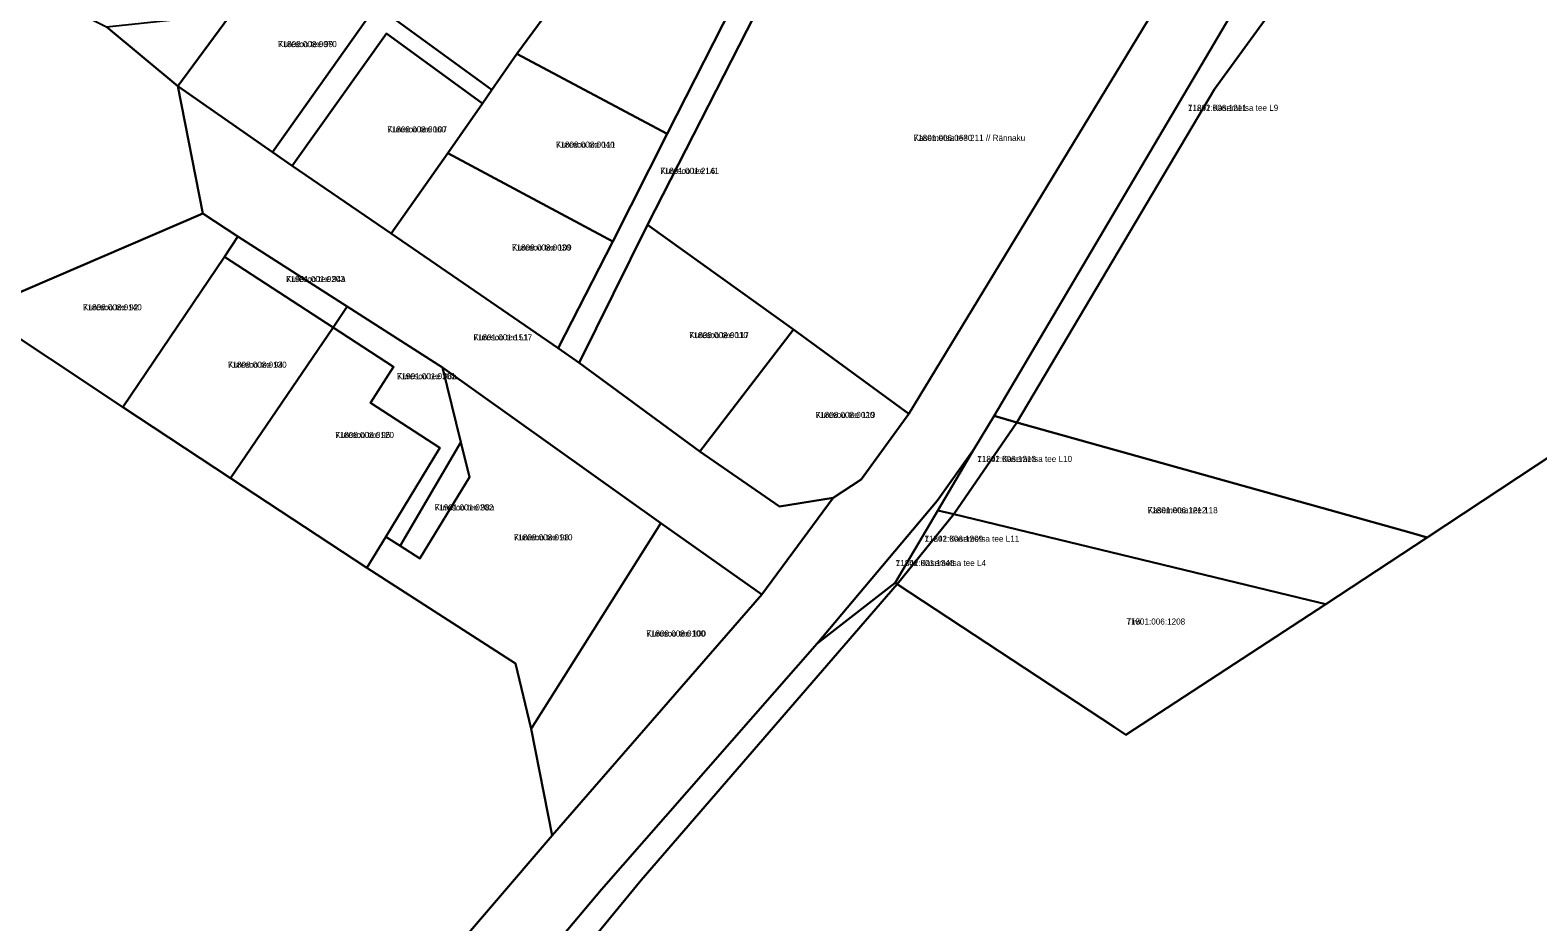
# Model space of a CAD drawing. Extents: x 529768 to 552006, y 6562269 to 6580975.
# Drawn here: x 537239.9 to 537612.3, y 6569100.3 to 6569320.5 of the extents above; entities that cross this region are included whole.
import ezdxf

# ---------------------------------------------------------------- set-up
doc = ezdxf.new("R2010")
doc.units = 0
for name, color, linetype in [('L_AADRESS', 7, 'Continuous'), ('PIIR', 7, 'Continuous'), ('TUNNUS', 7, 'Continuous')]:
    doc.layers.add(name, color=color, linetype=linetype)

msp = doc.modelspace()

# ---------------------------------------------------------------- linework, layer by layer
at = {"layer": 'PIIR'}
for points in [[(537281.43, 6569019.46), (537368.89, 6569121.58), (537420.6, 6569181.09), (537438.26, 6569204.93), (537445.15, 6569209.46), (537456.97, 6569225.74), (537523.87, 6569335.93), (537530.38, 6569351.64), (537552.48, 6569389.3), (537556.5, 6569395.83), (537567.78, 6569415.59), (537578.32, 6569433.84), (537588.9, 6569451.99), (537598.21, 6569467.74), (537645.8, 6569545.54), (537653.92, 6569559.3), (537664.42, 6569572.88), (537699.62, 6569634.71), (537702.59, 6569639.82), (537731.22, 6569689.57), (537747.58, 6569702.72), (538032.41, 6569935.34), (538189.88, 6570063.68)], [(537622.11, 6569470.11), (537568.68, 6569378.74), (537478.05, 6569225.23), (537473.1, 6569217.08), (537463.95, 6569204.19), (537434.3, 6569169.03), (537381.02, 6569108.28), (537348.18, 6569069.26)], [(537170.73, 6569376.5), (537249.6, 6569325.97), (537251.48, 6569325.01), (537257.63, 6569321.87), (537258.8, 6569321.28), (537276.4, 6569306.65), (537282.55, 6569275.19), (537226.88, 6569251.23), (537262.82, 6569227.37), (537289.45, 6569209.82), (537323.12, 6569187.65), (537359.8, 6569164.07), (537363.64, 6569147.9), (537368.89, 6569121.58), (537281.43, 6569019.46)], [(537269.76, 6568963.22), (537390.82, 6569110.56), (537454.04, 6569183.63), (537507.72, 6569148.32), (537510.55, 6569146.45), (537559.96, 6569178.74), (537584.93, 6569195.2), (537724.42, 6569287.32), (537727.95, 6569284.57), (537806.09, 6568987.59)]]:
    msp.add_lwpolyline(points, dxfattribs=at)
for points in [[(537331.41, 6569385.08), (537333.24, 6569383.74), (537303.05, 6569342.82), (537276.4, 6569306.65), (537258.8, 6569321.28), (537286.07, 6569324.15)], [(537568.68, 6569378.74), (537573.72, 6569375.48), (537557.07, 6569345.82), (537550.3, 6569330.48), (537532.46, 6569305.9), (537483.59, 6569223.61), (537478.05, 6569225.23)], [(537573.72, 6569375.48), (537721.35, 6569289.12), (537724.42, 6569287.32), (537584.93, 6569195.2), (537580.98, 6569196.31), (537483.59, 6569223.61), (537532.46, 6569305.9), (537550.3, 6569330.48), (537557.07, 6569345.82)], [(537356.02, 6569369.35), (537360.2, 6569366.7), (537329.49, 6569323.5), (537353.94, 6569305.69), (537351.65, 6569302.39), (537327.98, 6569319.65), (537304.66, 6569286.98), (537299.8, 6569290.36), (537325.92, 6569327.15)], [(537392.4, 6569272.37), (537420.72, 6569327.75), (537471.2, 6569369.35), (537523.87, 6569335.93), (537456.97, 6569225.74), (537428.48, 6569246.54)], [(537329.49, 6569323.5), (537360.2, 6569366.7), (537373.92, 6569357.84), (537386.16, 6569349.94), (537360.1, 6569314.6), (537353.94, 6569305.69)], [(537386.16, 6569349.94), (537415.64, 6569330.96), (537397.29, 6569294.89), (537360.1, 6569314.6)], [(537325.92, 6569327.15), (537299.8, 6569290.36), (537276.4, 6569306.65), (537303.05, 6569342.82)], [(537370.36, 6569241.96), (537383.8, 6569268.29), (537397.29, 6569294.89), (537415.64, 6569330.96), (537420.72, 6569327.75), (537392.4, 6569272.37), (537375.53, 6569238.29)], [(537327.98, 6569319.65), (537351.65, 6569302.39), (537343.1, 6569290.11), (537329.12, 6569270.23), (537304.66, 6569286.98)], [(537351.65, 6569302.39), (537353.94, 6569305.69), (537360.1, 6569314.6), (537397.29, 6569294.89), (537383.8, 6569268.29), (537343.1, 6569290.11)], [(537438.26, 6569204.93), (537420.6, 6569181.09), (537395.67, 6569198.74), (537341.76, 6569237.16), (537318.26, 6569252.2), (537291.25, 6569269.49), (537282.55, 6569275.19), (537276.4, 6569306.65), (537299.8, 6569290.36), (537304.66, 6569286.98), (537329.12, 6569270.23), (537370.36, 6569241.96), (537375.53, 6569238.29), (537405.33, 6569216.45), (537425.03, 6569202.85)], [(537383.8, 6569268.29), (537370.36, 6569241.96), (537329.12, 6569270.23), (537343.1, 6569290.11)], [(537282.55, 6569275.19), (537291.25, 6569269.49), (537287.93, 6569264.5), (537262.82, 6569227.37), (537226.88, 6569251.23)], [(537428.48, 6569246.54), (537405.33, 6569216.45), (537375.53, 6569238.29), (537392.4, 6569272.37)], [(537291.25, 6569269.49), (537318.26, 6569252.2), (537314.74, 6569247.04), (537287.93, 6569264.5)], [(537287.93, 6569264.5), (537314.74, 6569247.04), (537289.45, 6569209.82), (537262.82, 6569227.37)], [(537327.78, 6569195.35), (537341.1, 6569217.3), (537324.02, 6569228.41), (537329.65, 6569237.34), (537314.74, 6569247.04), (537318.26, 6569252.2), (537341.76, 6569237.16), (537346.31, 6569218.69), (537331.28, 6569193.13)], [(537314.74, 6569247.04), (537329.65, 6569237.34), (537324.02, 6569228.41), (537341.1, 6569217.3), (537327.78, 6569195.35), (537323.12, 6569187.65), (537289.45, 6569209.82)], [(537405.33, 6569216.45), (537428.48, 6569246.54), (537456.97, 6569225.74), (537445.15, 6569209.46), (537438.26, 6569204.93), (537425.03, 6569202.85)], [(537323.12, 6569187.65), (537327.78, 6569195.35), (537331.28, 6569193.13), (537336.2, 6569190), (537348.42, 6569210.1), (537346.31, 6569218.69), (537341.76, 6569237.16), (537395.67, 6569198.74), (537363.64, 6569147.9), (537359.8, 6569164.07)], [(537478.05, 6569225.23), (537483.59, 6569223.61), (537468.07, 6569200.9), (537464.1, 6569201.88), (537473.1, 6569217.08)], [(537483.59, 6569223.61), (537580.98, 6569196.31), (537584.93, 6569195.2), (537559.96, 6569178.74), (537555.84, 6569179.73), (537468.07, 6569200.9)], [(537336.2, 6569190), (537331.28, 6569193.13), (537346.31, 6569218.69), (537348.42, 6569210.1)], [(537463.95, 6569204.19), (537473.1, 6569217.08), (537464.1, 6569201.88), (537453.54, 6569183.95), (537434.3, 6569169.03)], [(537464.1, 6569201.88), (537468.07, 6569200.9), (537454.04, 6569183.63), (537453.54, 6569183.95)], [(537420.6, 6569181.09), (537368.89, 6569121.58), (537363.64, 6569147.9), (537395.67, 6569198.74)], [(537468.07, 6569200.9), (537555.84, 6569179.73), (537559.96, 6569178.74), (537510.55, 6569146.45), (537507.72, 6569148.32), (537454.04, 6569183.63)], [(537381.02, 6569108.28), (537434.3, 6569169.03), (537453.54, 6569183.95), (537454.04, 6569183.63), (537390.82, 6569110.56), (537269.76, 6568963.22), (537215.48, 6568889.87), (537209.84, 6568896.55), (537232.31, 6568928.74), (537261.02, 6568964.25), (537348.18, 6569069.26)]]:
    msp.add_lwpolyline(points, close=True, dxfattribs=at)

# ---------------------------------------------------------------- texts
at = {"layer": 'L_AADRESS'}
for s, p in [('Kuresoo tee 99', (537301.16, 6569316.27)), ('11242 Kasemetsa tee L9', (537525.88, 6569300.54)), ('Kuresoo tee 107', (537328.15, 6569295.21)), ('Kasemetsa tee 211 // Rännaku', (537458.13, 6569293.12)), ('Kuresoo tee 111', (537369.79, 6569291.45)), ('Kuresoo tee L6', (537395.54, 6569284.97)), ('Kuresoo tee 109', (537358.94, 6569266.04)), ('Kuresoo tee 94a', (537303.14, 6569258.26)), ('Kuresoo tee 92', (537252.99, 6569251.28)), ('Kuresoo tee 117', (537402.7, 6569244.41)), ('Kuresoo tee L1', (537349.42, 6569243.87)), ('Kuresoo tee 94', (537288.78, 6569237.1)), ('Kuresoo tee 96a', (537330.53, 6569234.26)), ('Kuresoo tee 119', (537433.94, 6569224.7)), ('Kuresoo tee 96', (537315.28, 6569219.75)), ('11242 Kasemetsa tee L10', (537473.85, 6569213.83)), ('Kuresoo tee 98a', (537339.85, 6569201.85)), ('Kasemetsa tee 118', (537515.94, 6569201.17)), ('Kuresoo tee 98', (537359.39, 6569194.46)), ('11242 Kasemetsa tee L11', (537460.8, 6569194.12)), ('11242 Kasemetsa tee L4', (537453.7, 6569188.13)), ('Tiivi', (537510.69, 6569173.67)), ('Kuresoo tee 100', (537392.12, 6569170.71))]:
    msp.add_text(s, height=1.5, dxfattribs=at).set_placement(p)
at = {"layer": 'TUNNUS'}
for s, p in [('71808:008:0070', (537301.16, 6569316.27)), ('71801:006:1211', (537525.88, 6569300.54)), ('71808:008:0060', (537328.15, 6569295.21)), ('71801:006:0630', (537458.13, 6569293.12)), ('71808:008:0040', (537369.79, 6569291.45)), ('71801:001:2141', (537395.54, 6569284.97)), ('71808:008:0030', (537358.94, 6569266.04)), ('71901:001:0203', (537303.14, 6569258.26)), ('71808:008:0140', (537252.99, 6569251.28)), ('71808:008:0010', (537402.7, 6569244.41)), ('71801:001:1517', (537349.42, 6569243.87)), ('71808:008:0130', (537288.78, 6569237.1)), ('71901:001:0201', (537330.53, 6569234.26)), ('71808:008:0020', (537433.94, 6569224.7)), ('71808:008:0120', (537315.28, 6569219.75)), ('71801:006:1213', (537473.85, 6569213.83)), ('71901:001:0202', (537339.85, 6569201.85)), ('71801:006:1212', (537515.94, 6569201.17)), ('71808:008:0110', (537359.39, 6569194.46)), ('71801:006:1209', (537460.8, 6569194.12)), ('71801:001:1348', (537453.7, 6569188.13)), ('71801:006:1208', (537510.69, 6569173.67)), ('71808:008:0100', (537392.12, 6569170.71))]:
    msp.add_text(s, height=1.5, dxfattribs=at).set_placement(p)

doc.saveas('drawing.dxf')
